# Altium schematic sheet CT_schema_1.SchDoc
size 519 x 258 mm
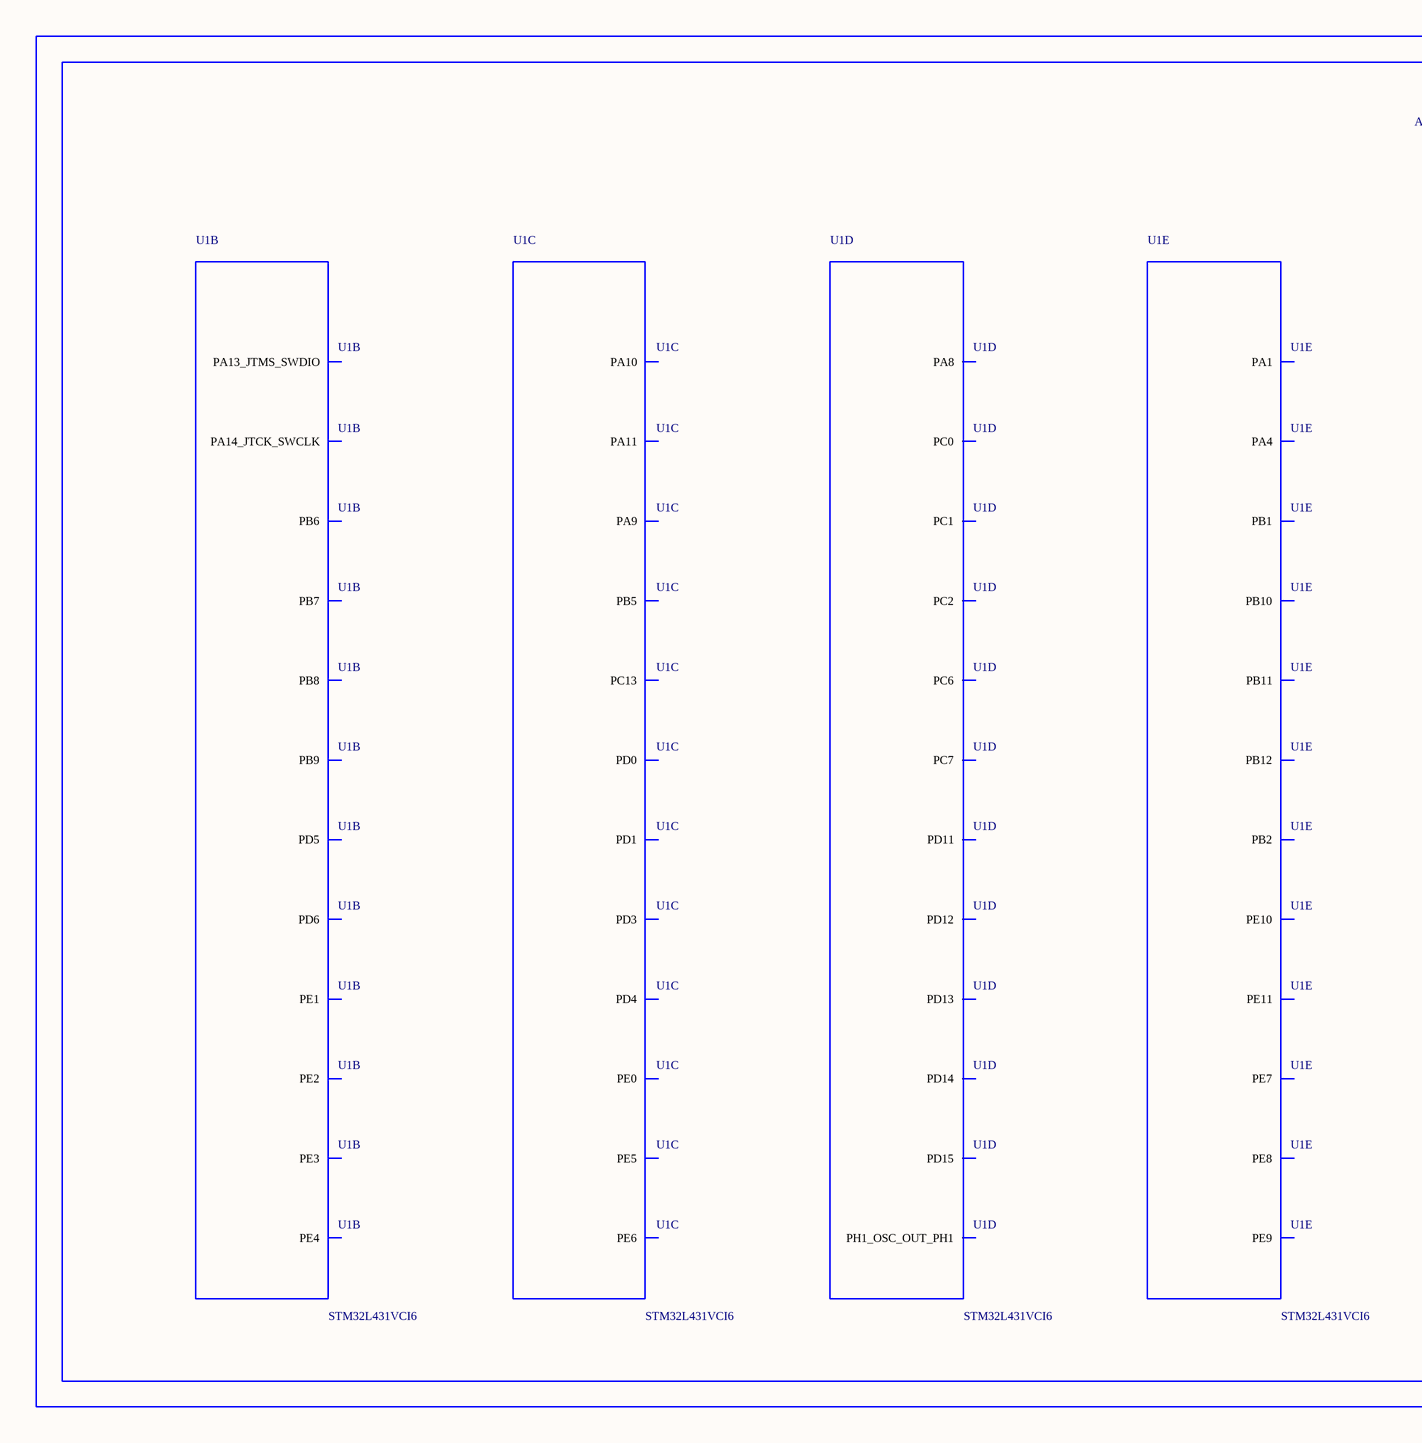
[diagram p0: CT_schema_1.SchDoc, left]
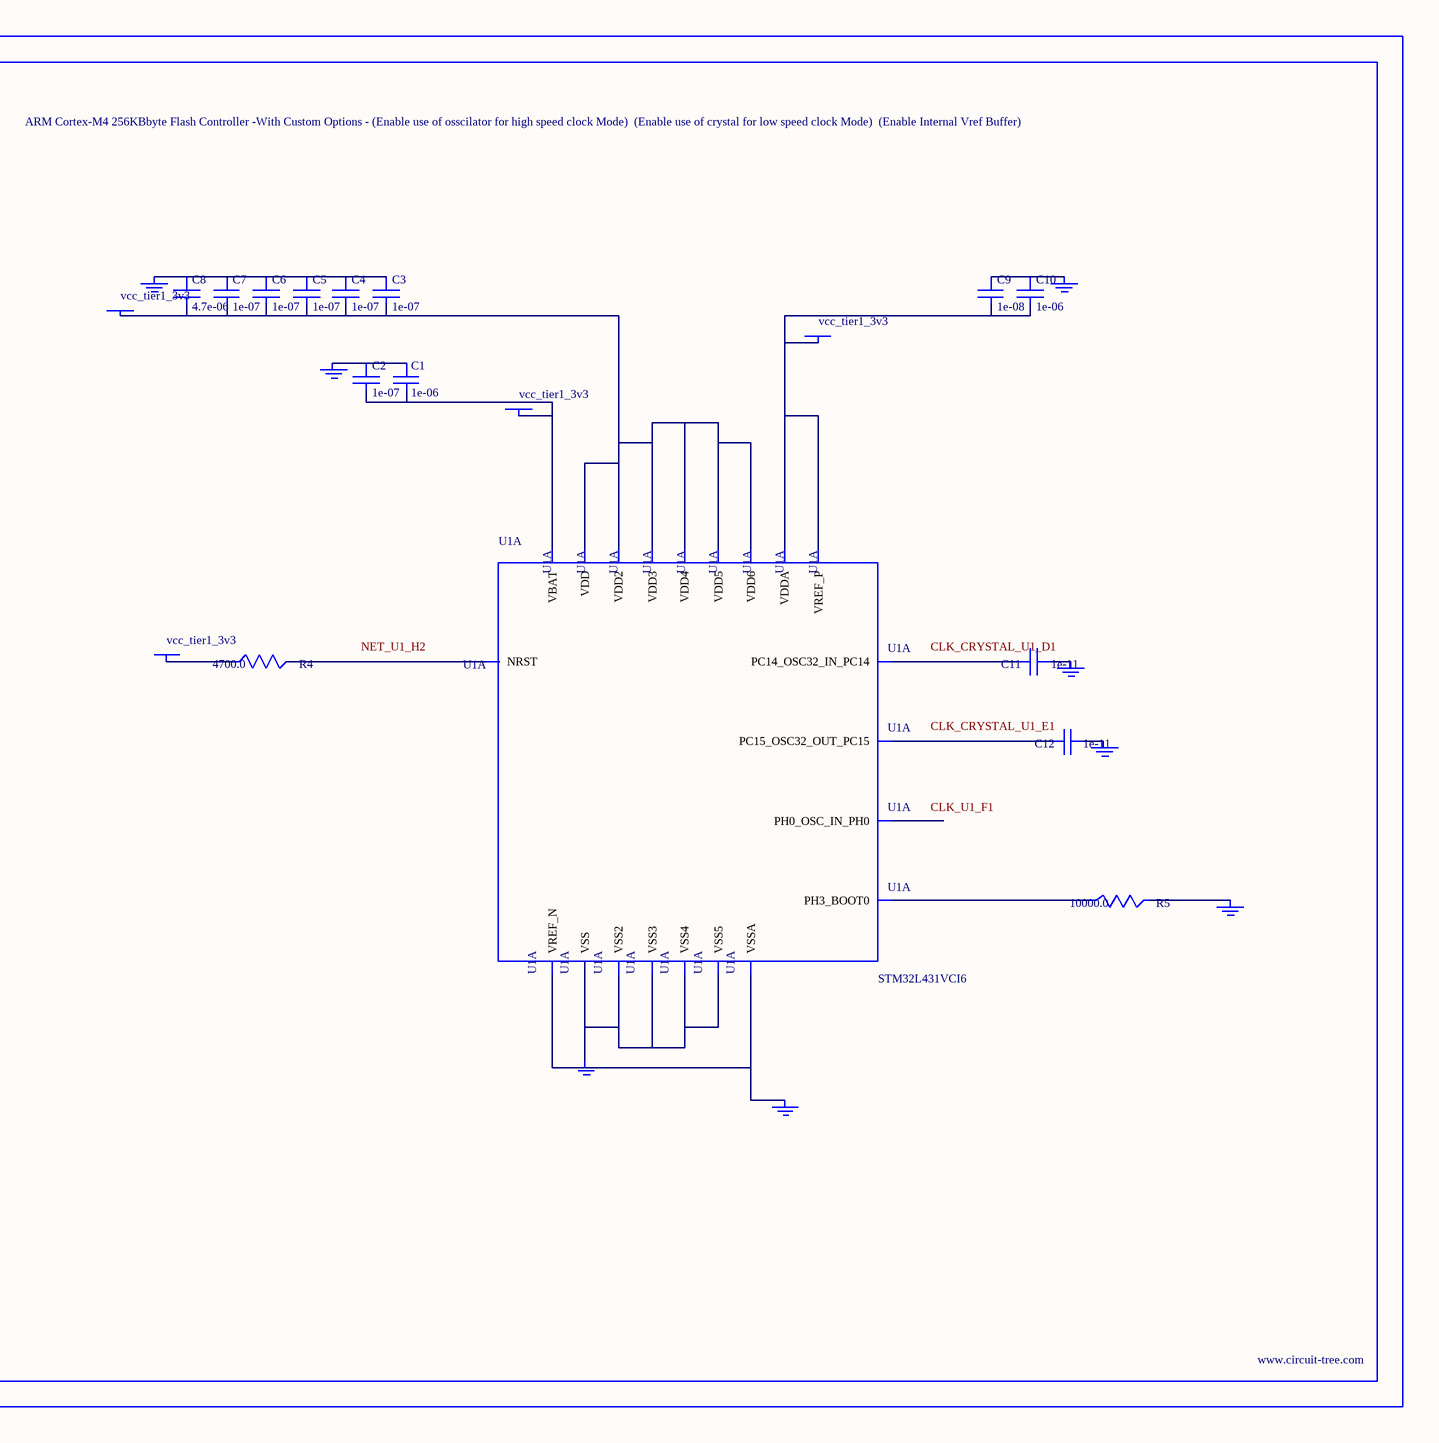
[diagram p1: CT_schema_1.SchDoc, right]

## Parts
BORDER0  (no value)
C1  1e-06  [C0603]
C2  1e-07  [C0603]
C3  1e-07  [C0603]
C4  1e-07  [C0603]
C5  1e-07  [C0603]
C6  1e-07  [C0603]
C7  1e-07  [C0603]
C8  4.7e-06  [C0603]
C9  1e-08  [C0603]
C10  1e-06  [C0603]
C11  1e-11  [C0402]
C12  1e-11  [C0402]
GND_INSTANCE_0_0  (no value)
GND_INSTANCE_0_1  (no value)
GND_INSTANCE_0_2  (no value)
GND_INSTANCE_0_3  (no value)
GND_INSTANCE_0_4  (no value)
GND_INSTANCE_0_5  (no value)
GND_INSTANCE_0_6  (no value)
GND_INSTANCE_0_7  (no value)
POWER_INSTANCE_0_0  vcc_tier1_3v3
POWER_INSTANCE_0_1  vcc_tier1_3v3
POWER_INSTANCE_0_2  vcc_tier1_3v3
POWER_INSTANCE_0_3  vcc_tier1_3v3
R4  4700.0  [R0603]
R5  10000.0  [R0603]
U1  STM32L431VCI6  [UFBGA100]  (parts A,B,C,D,E of 9)

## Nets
NetC1_1: C1.1 C2.1 GND_INSTANCE_0_0.0(GND)
NetC1_2: C1.2 C2.2 POWER_INSTANCE_0_0.0(PWR) U1.E2(VBAT)
NetC3_1: C3.1 C4.1 C5.1 C6.1 C7.1 C8.1 GND_INSTANCE_0_1.0(GND)
NetC3_2: C3.2 C4.2 C5.2 C6.2 C7.2 C8.2 POWER_INSTANCE_0_1.0(PWR) U1.C4(VDD2) U1.C11(VDD) U1.G2(VDD5) U1.G11(VDD3) U1.G12(VDD4) U1.H3(VDD6)
NetC9_1: C9.1 C10.1 GND_INSTANCE_0_3.0(GND)
NetC9_2: C9.2 C10.2 POWER_INSTANCE_0_2.0(PWR) U1.L1(VREF_P) U1.M1(VDDA)
NetC11_1: C11.1 GND_INSTANCE_0_4.0(GND)
NetC11_2: C11.2 U1.D1(PC14_OSC32_IN_PC14)
NetC12_1: C12.1 GND_INSTANCE_0_5.0(GND)
NetC12_2: C12.2 U1.E1(PC15_OSC32_OUT_PC15)
NetGND_INSTANCE_0_2_0: GND_INSTANCE_0_2.0(GND) R5.2
NetGND_INSTANCE_0_6_0: GND_INSTANCE_0_6.0(GND) U1.J1(VSSA) U1.K1(VREF_N)
NetGND_INSTANCE_0_7_0: GND_INSTANCE_0_7.0(GND) U1.D3(VSS) U1.E3(VSS2) U1.F2(VSS5) U1.F11(VSS3) U1.F12(VSS4)
NetPOWER_INSTANCE_0_3_0: POWER_INSTANCE_0_3.0(PWR) R4.1
NetR4_2: R4.2 U1.H2(NRST)
NetR5_1: R5.1 U1.A4(PH3_BOOT0)

Not connected (* = marked no-connect by the designer): U1 A1(PE3) A2(PE1) A3(PB8) A6(PD5) A10(PA14_JTCK_SWCLK) A11(PA13_JTMS_SWDIO) B1(PE4) B2(PE2) B3(PB9) B4(PB7) B5(PB6) B6(PD6) B7(PD4) B8(PD3) B9(PD1) B12(PA11) C1(PC13) C2(PE5) C3(PE0) C5(PB5) C9(PD0) C12(PA10) D2(PE6) D10(PA9) D11(PA8) E11(PC7) E12(PC6) F1(PH0_OSC_IN_PH0) G1(PH1_OSC_OUT_PH1) H1(PC0) H10(PD15) H11(PD14) H12(PD13) J2(PC1) J3(PC2) J10(PD12) J11(PD11) L6(PB2) L7(PE8) L8(PE10) L10(PB10) L11(PB11) L12(PB12) M2(PA1) M3(PA4) M6(PB1) M7(PE7) M8(PE9) M9(PE11)

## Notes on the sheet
- Labels drawn without touching a wire or pin: CLK_CRYSTAL_U1_D1, CLK_CRYSTAL_U1_E1, CLK_U1_F1, NET_U1_H2

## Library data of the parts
BORDER0 = BORDER_PAGE0
C1 C10 = C0603C105K3RACTU
C2-C7 = 06035C104K4Z2A
C8 = GRM188R6YA475KE15D
C9 = 06035C103K4Z2A
C11 C12 = C0402C100K3GACTU
GND_INSTANCE_0_0-GND_INSTANCE_0_7 = GND
POWER_INSTANCE_0_0-POWER_INSTANCE_0_3 = PWR
R4 = RC0603JR-074K7L
R5 = RC0603JR-0710KL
